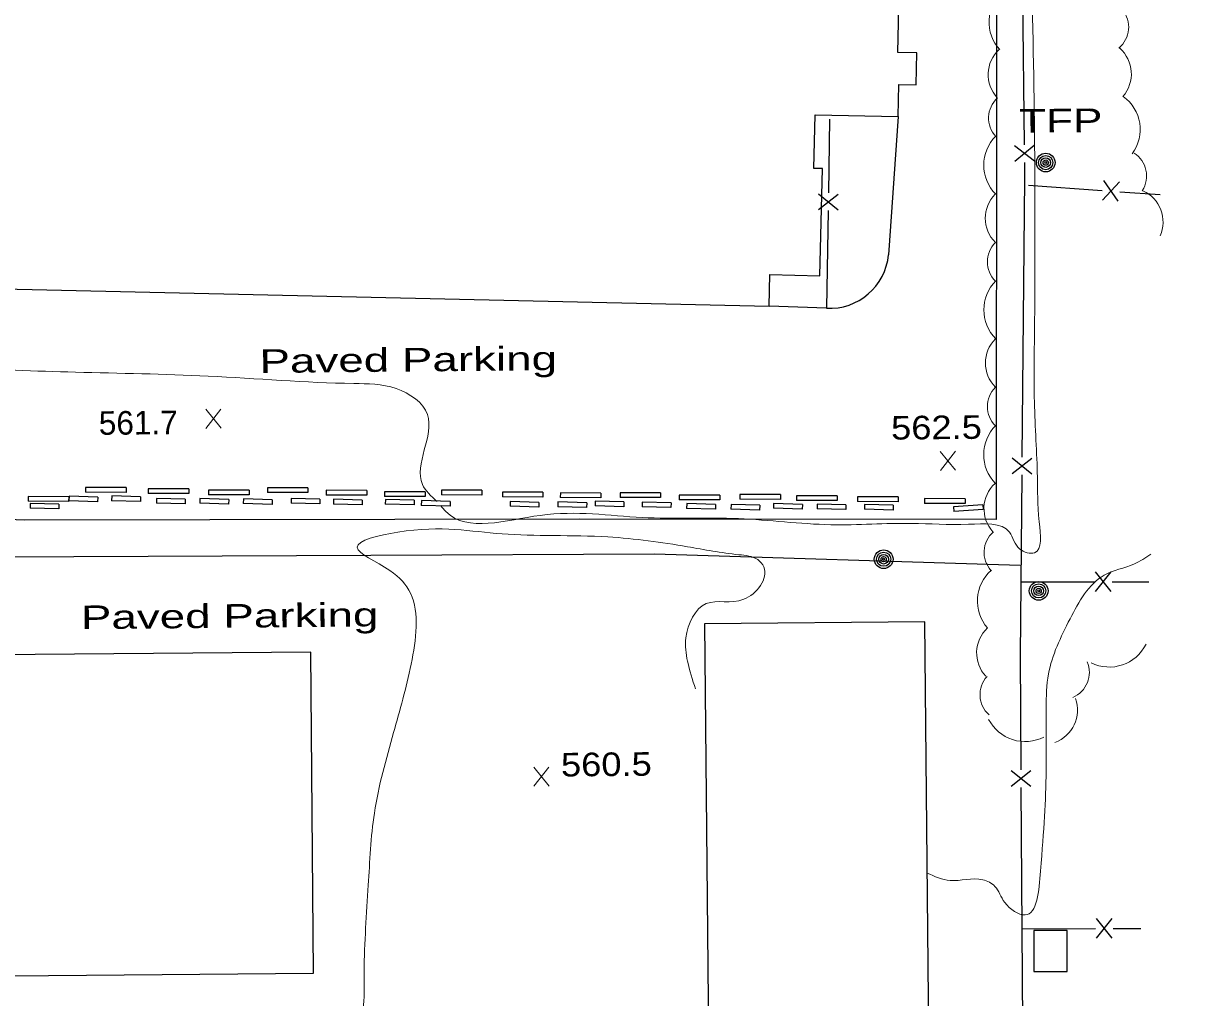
# Model space of a CAD drawing. Extents: x 2361708 to 2370558, y 6977955 to 6991887.
# Drawn here: x 2366784.3 to 2367023.7, y 6986283.9 to 6986482.1 of the extents above; entities that cross this region are included whole.
import ezdxf

# ---------------------------------------------------------------- set-up
doc = ezdxf.new("R2010")
doc.units = 0
doc.header["$LTSCALE"] = 1.9
for name, color, linetype, lineweight in [('11', 7, 'Continuous', 25), ('17', 7, 'Continuous', 25), ('2', 7, 'Continuous', 25), ('20', 7, 'Continuous', 25), ('29', 7, 'Continuous', 13), ('31', 7, 'Continuous', 13), ('35', 7, 'Continuous', 13)]:
    doc.layers.add(name, color=color, linetype=linetype, lineweight=lineweight)

msp = doc.modelspace()

# ---------------------------------------------------------------- linework, layer by layer
at = {"layer": '11'}
for points in [[(2366725.976, 6986429.298), (2366936.012, 6986424.548), (2366936.16, 6986430.989), (2366946.333, 6986430.756), (2366946.826, 6986452.562), (2366945.105, 6986452.595), (2366945.332, 6986463.498), (2366962.235, 6986463.149), (2366962.364, 6986469.641), (2366965.885, 6986469.564), (2366966.022, 6986476.116), (2366962.191, 6986476.199), (2366962.972, 6986512.868), (2366938.416, 6986513.395), (2366940.255, 6986599.697), (2366765.561, 6986603.424), (2366765.653, 6986607.385), (2366726.593, 6986608.243), (2366724.888, 6986531.023), (2366728.349, 6986530.946)], [(2366969.575, 6986164.925), (2366967.665, 6986360.326), (2366922.817, 6986359.889), (2366924.717, 6986164.488)], [(2366842.777, 6986354.187), (2366642.464, 6986352.45), (2366643.026, 6986287.103), (2366843.339, 6986288.829)], [(2366989.853, 6986297.534), (2366989.813, 6986289.173), (2366996.603, 6986289.148), (2366996.634, 6986297.509)]]:
    msp.add_lwpolyline(points, close=True, dxfattribs=at)
at = {"layer": '17'}
for p, q in [((2366987.941, 6986457.414), (2366987.23, 6986517.41)), ((2366948.3, 6986462.606), (2366948.043, 6986447.613)), ((2366989.954, 6986454.033), (2366985.914, 6986457.184)), ((2366989.914, 6986457.232), (2366985.954, 6986453.985)), ((2366988.77, 6986449.161), (2367003.731, 6986448.103)), ((2367003.79, 6986446.124), (2367007.264, 6986449.887)), ((2367006.982, 6986445.894), (2367004.072, 6986450.117)), ((2366946.015, 6986444.244), (2366950.065, 6986447.373)), ((2366946.065, 6986447.444), (2366950.016, 6986444.172)), ((2367007.323, 6986447.848), (2367015.549, 6986447.266)), ((2366989.449, 6986393.595), (2366985.419, 6986390.436)), ((2366989.42, 6986390.394), (2366985.458, 6986393.637)), ((2367002.368, 6986366.516), (2367005.57, 6986370.517)), ((2367005.568, 6986366.516), (2367002.369, 6986370.516)), ((2366987.168, 6986368.462), (2367002.169, 6986368.485)), ((2367005.768, 6986368.489), (2367013.229, 6986368.5)), ((2366989.245, 6986326.829), (2366985.224, 6986330.001)), ((2366989.224, 6986330.029), (2366985.245, 6986326.801)), ((2366987.667, 6986266.622), (2366987.276, 6986326.621)), ((2367005.789, 6986295.956), (2367002.571, 6986299.945)), ((2367002.589, 6986295.945), (2367005.771, 6986299.956)), ((2366987.38, 6986297.85), (2367002.38, 6986297.913)), ((2367005.98, 6986297.927), (2367011.58, 6986297.951))]:
    msp.add_line(p, q, dxfattribs=at)
for points in [[(2366987.487, 6986393.816), (2366988.027, 6986450.534), (2366987.986, 6986453.814)], [(2366947.977, 6986444.012), (2366947.636, 6986424.128), (2366936.012, 6986424.548)], [(2366987.252, 6986330.221), (2366987.101, 6986353.501), (2366987.451, 6986390.216)]]:
    msp.add_lwpolyline(points, dxfattribs=at)
at = {"layer": '2'}
for p, q in [((2366962.235, 6986463.149), (2366960.293, 6986435.029)), ((2366793.573, 6986385.89), (2366793.542, 6986384.929)), ((2366799.415, 6986385.725), (2366793.573, 6986385.89)), ((2366796.946, 6986387.652), (2366796.945, 6986386.692)), ((2366805.196, 6986386.671), (2366796.945, 6986386.692)), ((2366805.197, 6986387.63), (2366796.946, 6986387.652)), ((2366802.273, 6986385.933), (2366802.242, 6986384.972)), ((2366808.115, 6986385.768), (2366802.273, 6986385.933)), ((2366805.197, 6986387.63), (2366805.196, 6986386.671)), ((2366809.679, 6986387.413), (2366809.678, 6986386.453)), ((2366817.929, 6986386.432), (2366809.678, 6986386.453)), ((2366817.93, 6986387.392), (2366809.679, 6986387.413)), ((2366817.93, 6986387.392), (2366817.929, 6986386.432)), ((2366821.953, 6986387.12), (2366821.952, 6986386.16)), ((2366830.202, 6986386.139), (2366821.952, 6986386.16)), ((2366830.203, 6986387.099), (2366821.953, 6986387.12)), ((2366830.203, 6986387.099), (2366830.202, 6986386.139)), ((2366833.938, 6986387.624), (2366833.937, 6986386.664)), ((2366842.188, 6986386.642), (2366833.937, 6986386.664)), ((2366842.189, 6986387.603), (2366833.938, 6986387.624)), ((2366842.189, 6986387.603), (2366842.188, 6986386.642)), ((2366845.894, 6986387.088), (2366845.893, 6986386.128)), ((2366854.143, 6986386.106), (2366845.893, 6986386.128)), ((2366854.145, 6986387.066), (2366845.894, 6986387.088)), ((2366854.145, 6986387.066), (2366854.143, 6986386.106)), ((2366857.758, 6986386.801), (2366857.757, 6986385.841)), ((2366866.008, 6986386.779), (2366857.758, 6986386.801)), ((2366866.008, 6986386.779), (2366866.007, 6986385.819)), ((2366869.315, 6986387.111), (2366869.314, 6986386.151)), ((2366877.565, 6986386.13), (2366869.314, 6986386.151)), ((2366877.565, 6986387.09), (2366869.315, 6986387.111)), ((2366877.565, 6986387.09), (2366877.565, 6986386.13)), ((2366889.98, 6986386.688), (2366881.729, 6986386.709)), ((2366881.729, 6986386.709), (2366881.729, 6986385.749)), ((2366889.98, 6986386.688), (2366889.979, 6986385.728)), ((2366893.521, 6986386.561), (2366893.52, 6986385.601)), ((2366901.772, 6986386.54), (2366893.521, 6986386.561)), ((2366901.772, 6986386.54), (2366901.771, 6986385.58)), ((2366905.672, 6986386.577), (2366905.671, 6986385.617)), ((2366913.922, 6986386.555), (2366905.672, 6986386.577)), ((2366913.922, 6986386.555), (2366913.922, 6986385.595)), ((2366917.707, 6986386.111), (2366917.706, 6986385.152)), ((2366925.957, 6986386.09), (2366917.707, 6986386.111)), ((2366925.957, 6986386.09), (2366925.957, 6986385.13)), ((2366930.026, 6986386.229), (2366930.025, 6986385.269)), ((2366938.277, 6986386.207), (2366930.026, 6986386.229)), ((2366938.277, 6986386.207), (2366938.276, 6986385.247)), ((2366941.569, 6986385.978), (2366941.568, 6986385.018)), ((2366949.82, 6986385.957), (2366941.569, 6986385.978)), ((2366949.82, 6986385.957), (2366949.819, 6986384.997)), ((2366785.253, 6986385.811), (2366785.252, 6986384.85)), ((2366793.503, 6986384.829), (2366785.252, 6986384.85)), ((2366793.504, 6986385.789), (2366785.253, 6986385.811)), ((2366785.687, 6986384.415), (2366785.656, 6986383.454)), ((2366791.528, 6986384.25), (2366785.687, 6986384.415)), ((2366791.528, 6986384.25), (2366791.498, 6986383.29)), ((2366793.504, 6986385.789), (2366793.503, 6986384.829)), ((2366799.384, 6986384.765), (2366793.542, 6986384.929)), ((2366799.415, 6986385.725), (2366799.384, 6986384.765)), ((2366808.084, 6986384.808), (2366802.242, 6986384.972)), ((2366808.115, 6986385.768), (2366808.084, 6986384.808)), ((2366811.378, 6986385.439), (2366811.347, 6986384.479)), ((2366817.189, 6986384.315), (2366811.347, 6986384.479)), ((2366817.22, 6986385.275), (2366811.378, 6986385.439)), ((2366817.22, 6986385.275), (2366817.189, 6986384.315)), ((2366820.219, 6986385.404), (2366820.188, 6986384.443)), ((2366826.03, 6986384.279), (2366820.188, 6986384.443)), ((2366826.06, 6986385.239), (2366820.219, 6986385.404)), ((2366826.06, 6986385.239), (2366826.03, 6986384.279)), ((2366829.06, 6986385.338), (2366829.029, 6986384.377)), ((2366834.871, 6986384.213), (2366829.029, 6986384.377)), ((2366834.902, 6986385.173), (2366829.06, 6986385.338)), ((2366834.902, 6986385.173), (2366834.871, 6986384.213)), ((2366838.769, 6986385.43), (2366838.739, 6986384.47)), ((2366844.58, 6986384.305), (2366838.739, 6986384.47)), ((2366844.612, 6986385.266), (2366838.769, 6986385.43)), ((2366844.612, 6986385.266), (2366844.58, 6986384.305)), ((2366847.391, 6986385.262), (2366847.361, 6986384.302)), ((2366853.202, 6986384.137), (2366847.361, 6986384.302)), ((2366853.233, 6986385.098), (2366847.391, 6986385.262)), ((2366853.233, 6986385.098), (2366853.202, 6986384.137)), ((2366866.007, 6986385.819), (2366857.757, 6986385.841)), ((2366857.942, 6986385.233), (2366857.911, 6986384.272)), ((2366863.753, 6986384.108), (2366857.911, 6986384.272)), ((2366863.784, 6986385.068), (2366857.942, 6986385.233)), ((2366863.784, 6986385.068), (2366863.753, 6986384.108)), ((2366865.275, 6986384.982), (2366865.244, 6986384.022)), ((2366871.086, 6986383.858), (2366865.244, 6986384.022)), ((2366871.116, 6986384.818), (2366865.275, 6986384.982)), ((2366871.116, 6986384.818), (2366871.086, 6986383.858)), ((2366889.979, 6986385.728), (2366881.729, 6986385.749)), ((2366883.337, 6986384.804), (2366883.306, 6986383.844)), ((2366889.149, 6986383.679), (2366883.306, 6986383.844)), ((2366889.179, 6986384.64), (2366883.337, 6986384.804)), ((2366889.179, 6986384.64), (2366889.149, 6986383.679)), ((2366893.039, 6986384.717), (2366893.008, 6986383.756)), ((2366898.85, 6986383.592), (2366893.008, 6986383.756)), ((2366898.881, 6986384.552), (2366893.039, 6986384.717)), ((2366901.771, 6986385.58), (2366893.52, 6986385.601)), ((2366898.881, 6986384.552), (2366898.85, 6986383.592)), ((2366900.627, 6986384.879), (2366900.596, 6986383.919)), ((2366906.439, 6986383.754), (2366900.596, 6986383.919)), ((2366906.469, 6986384.715), (2366900.627, 6986384.879)), ((2366913.922, 6986385.595), (2366905.671, 6986385.617)), ((2366906.469, 6986384.715), (2366906.439, 6986383.754)), ((2366910.2, 6986384.7), (2366910.169, 6986383.739)), ((2366916.011, 6986383.575), (2366910.169, 6986383.739)), ((2366916.042, 6986384.536), (2366910.2, 6986384.7)), ((2366916.042, 6986384.536), (2366916.011, 6986383.575)), ((2366925.957, 6986385.13), (2366917.706, 6986385.152)), ((2366919.243, 6986384.376), (2366919.212, 6986383.416)), ((2366925.085, 6986384.212), (2366919.243, 6986384.376)), ((2366925.085, 6986384.212), (2366925.054, 6986383.251)), ((2366928.245, 6986384.202), (2366928.214, 6986383.241)), ((2366934.087, 6986384.037), (2366928.245, 6986384.202)), ((2366938.276, 6986385.247), (2366930.025, 6986385.269)), ((2366934.087, 6986384.037), (2366934.056, 6986383.077)), ((2366936.914, 6986384.384), (2366936.883, 6986383.424)), ((2366942.756, 6986384.22), (2366936.914, 6986384.384)), ((2366949.819, 6986384.997), (2366941.568, 6986385.018)), ((2366942.756, 6986384.22), (2366942.725, 6986383.26)), ((2366945.786, 6986384.279), (2366945.755, 6986383.319)), ((2366951.627, 6986384.114), (2366945.786, 6986384.279)), ((2366951.627, 6986384.114), (2366951.597, 6986383.154)), ((2366953.962, 6986385.757), (2366953.961, 6986384.797)), ((2366962.211, 6986384.775), (2366953.961, 6986384.797)), ((2366962.212, 6986385.735), (2366953.962, 6986385.757)), ((2366955.397, 6986384.2), (2366955.366, 6986383.24)), ((2366961.238, 6986384.036), (2366955.397, 6986384.2)), ((2366961.238, 6986384.036), (2366961.208, 6986383.075)), ((2366962.212, 6986385.735), (2366962.211, 6986384.775)), ((2366967.626, 6986385.397), (2366967.625, 6986384.437)), ((2366975.875, 6986384.415), (2366967.625, 6986384.437)), ((2366975.876, 6986385.375), (2366967.626, 6986385.397)), ((2366979.478, 6986384.129), (2366973.482, 6986383.742)), ((2366973.482, 6986383.742), (2366973.541, 6986382.783)), ((2366975.876, 6986385.375), (2366975.875, 6986384.415)), ((2366979.478, 6986384.129), (2366979.538, 6986383.17)), ((2366791.498, 6986383.29), (2366785.656, 6986383.454)), ((2366925.054, 6986383.251), (2366919.212, 6986383.416)), ((2366934.056, 6986383.077), (2366928.214, 6986383.241)), ((2366942.725, 6986383.26), (2366936.883, 6986383.424)), ((2366951.597, 6986383.154), (2366945.755, 6986383.319)), ((2366961.208, 6986383.075), (2366955.366, 6986383.24)), ((2366979.538, 6986383.17), (2366973.541, 6986382.783))]:
    msp.add_line(p, q, dxfattribs=at)
for points in [[(2366978.777, 6986730.96), (2366980.486, 6986631.291), (2366982.347, 6986568.135), (2366982.177, 6986381.135), (2366897.512, 6986381.199), (2366784.559, 6986380.984), (2366694.932, 6986384.401), (2366631.052, 6986388.343)], [(2366613.139, 6986372.802), (2366854.95, 6986373.904), (2366912.65, 6986374.183), (2366987.036, 6986371.861)]]:
    msp.add_lwpolyline(points, dxfattribs=at)
msp.add_arc((2366948.278, 6986436.182), 12.07, 266.95249, 354.52088, dxfattribs=at)
at = {"layer": '20'}
for centre, radius in [((2366992.256, 6986453.774), 1.9), ((2366992.256, 6986453.774), 1.442), ((2366992.256, 6986453.774), 0.973), ((2366992.256, 6986453.774), 0.539), ((2366992.256, 6986453.774), 0.192), ((2366959.293, 6986373.067), 1.9), ((2366959.293, 6986373.067), 1.442), ((2366959.293, 6986373.067), 0.973), ((2366959.293, 6986373.067), 0.539), ((2366959.293, 6986373.067), 0.192), ((2366990.826, 6986366.627), 1.9), ((2366990.826, 6986366.627), 1.442), ((2366990.826, 6986366.627), 0.973), ((2366990.826, 6986366.627), 0.539), ((2366990.826, 6986366.627), 0.192)]:
    msp.add_circle(centre, radius, dxfattribs=at)
at = {"layer": '29'}
for centre, radius, start, end in [((2366989.069, 6986482.389), 8.339, 132.28995, 222.28995), ((2367003.584, 6986481.347), 5.556, 309.64887, 39.64887), ((2367002.729, 6986471.811), 6.953, 318.82266, 48.82266), ((2366987.506, 6986471.689), 6.953, 132.90887, 222.90887), ((2366986.2, 6986462.861), 5.556, 132.90887, 222.90887), ((2367003.135, 6986460.5), 8.339, 323.90841, 53.90841), ((2366987.99, 6986453.258), 8.339, 135.04904, 225.04904), ((2367007.227, 6986451.044), 5.556, 327.36333, 57.36333), ((2366986.927, 6986442.443), 6.953, 135.04904, 225.04904), ((2367009.182, 6986441.699), 6.953, 335.83715, 65.83715), ((2366985.951, 6986433.572), 5.556, 135.04845, 225.04845), ((2366988.015, 6986423.818), 8.339, 135.04845, 225.04845), ((2366986.943, 6986412.993), 6.953, 134.93627, 224.93627), ((2366985.95, 6986404.124), 5.556, 134.93627, 224.93627), ((2366987.976, 6986394.355), 8.339, 134.82257, 224.82257), ((2366986.65, 6986383.359), 6.953, 132.60291, 222.60291), ((2366985.281, 6986374.449), 5.556, 131.29451, 221.29451), ((2366986.701, 6986364.581), 8.339, 131.29451, 221.29451), ((2366985.158, 6986353.998), 6.953, 133.05384, 223.05384), ((2367005.203, 6986359.47), 8.339, 243.5438, 333.5438), ((2366995.593, 6986350.064), 5.556, 292.76574, 22.76574), ((2366984.452, 6986345.498), 5.556, 137.84636, 227.84636), ((2366991.755, 6986342.323), 6.953, 290.06174, 20.06174), ((2366988.06, 6986344.301), 8.339, 207.27762, 297.27762)]:
    msp.add_arc(centre, radius, start, end, dxfattribs=at)
at = {"layer": '31'}
for p, q in [((2366824.502, 6986399.725), (2366821.386, 6986403.575)), ((2366821.423, 6986399.696), (2366824.466, 6986403.605)), ((2366973.931, 6986391.157), (2366970.814, 6986395.007)), ((2366970.852, 6986391.128), (2366973.895, 6986395.037)), ((2366891.229, 6986326.887), (2366888.112, 6986330.737)), ((2366888.149, 6986326.857), (2366891.192, 6986330.766))]:
    msp.add_line(p, q, dxfattribs=at)
at = {"layer": '35'}
for points in [[(2367023.738, 6986749.948), (2367013.619, 6986749.852), (2367006.6, 6986748.605), (2366995.444, 6986747.209), (2366990.341, 6986745.34), (2366990, 6986739.157), (2366989.915, 6986722.865), (2366991.127, 6986704.756), (2366991.887, 6986673.251), (2366988.481, 6986650.758), (2366987.352, 6986641.137), (2366987.053, 6986622.203), (2366986.833, 6986605.37), (2366986.743, 6986590.688), (2366986.997, 6986562.91), (2366987.687, 6986533.495), (2366987.954, 6986521.247), (2366989.38, 6986488.059), (2366990.04, 6986450.193), (2366989.98, 6986419.741), (2366989.959, 6986405.09), (2366990.565, 6986389.845), (2366990.942, 6986380.648), (2366989.972, 6986374.369), (2366986.994, 6986375.141), (2366984.882, 6986378.551), (2366976.556, 6986380.181), (2366965.014, 6986380.362), (2366948.545, 6986380.094), (2366929.743, 6986381.326), (2366910.19, 6986381.56), (2366889.415, 6986381.992), (2366870.226, 6986382.78), (2366869.195, 6986383.97)], [(2366868.457, 6986384.822), (2366865.474, 6986388.284), (2366866.498, 6986402.495), (2366860.138, 6986407.784), (2366851.487, 6986408.822), (2366821.872, 6986410.331), (2366794.873, 6986411.133), (2366770.463, 6986412.031), (2366743.627, 6986413.606), (2366725.518, 6986415.484), (2366710.239, 6986419.488), (2366701.568, 6986428.006), (2366698.679, 6986441.48), (2366695.485, 6986459.8), (2366692.971, 6986476.927), (2366692.195, 6986496.53), (2366693.808, 6986515.126), (2366698.154, 6986534.509), (2366700.997, 6986560.417), (2366709.202, 6986587.256), (2366717.142, 6986600.983), (2366721.875, 6986602.788), (2366722.497, 6986614.094), (2366724.46, 6986616.983)], [(2366921.022, 6986346.661), (2366919.399, 6986352.296), (2366919.063, 6986357.103), (2366923.207, 6986364.033), (2366930.839, 6986364.915), (2366934.906, 6986371.504), (2366933.682, 6986372.983), (2366929.833, 6986373.986), (2366919.387, 6986375.607), (2366903.197, 6986377.603), (2366881.67, 6986378.218), (2366860.446, 6986378.576), (2366852.185, 6986375.508), (2366858.83, 6986370.78), (2366863.034, 6986366.15), (2366863.161, 6986351.741), (2366859.604, 6986337.776), (2366855.69, 6986321.408), (2366854.459, 6986306.746), (2366853.617, 6986289.087), (2366852.06, 6986276.131), (2366847.756, 6986270.28), (2366838.679, 6986263.633), (2366836.582, 6986263.343)], [(2367013.656, 6986374.064), (2367010.294, 6986372.132), (2367004.136, 6986369.793), (2366997.21, 6986360.927), (2366992.827, 6986349.715), (2366992.332, 6986342.8), (2366992.344, 6986330.029), (2366991.218, 6986309.618), (2366988.053, 6986300.697), (2366983.919, 6986303.228), (2366981.918, 6986306.499), (2366979.465, 6986307.825), (2366972.815, 6986307.712), (2366968.121, 6986309.208)]]:
    msp.add_spline(points, degree=3, dxfattribs=at)

# ---------------------------------------------------------------- texts
at = {"layer": '2', "width": 1.45}
for p in [(2366832.336, 6986410.97), (2366796.011, 6986358.832)]:
    msp.add_text('Paved Parking', height=4.8, rotation=0.545, dxfattribs=at).set_placement(p)
at = {"layer": '20', "width": 1.4}
msp.add_text('  TFP', height=4.8, rotation=0.545, dxfattribs=at).set_placement((2366981.858, 6986459.796))
at = {"layer": '31'}
msp.add_text('561.7', height=4.8, rotation=0.545, dxfattribs=at).set_placement((2366799.654, 6986398.368))
at = {"layer": '31', "width": 1.15}
for s, p in [('562.5', (2366960.821, 6986397.403)), ('560.5', (2366893.671, 6986328.85))]:
    msp.add_text(s, height=4.8, rotation=0.545, dxfattribs=at).set_placement(p)

doc.saveas('drawing.dxf')
